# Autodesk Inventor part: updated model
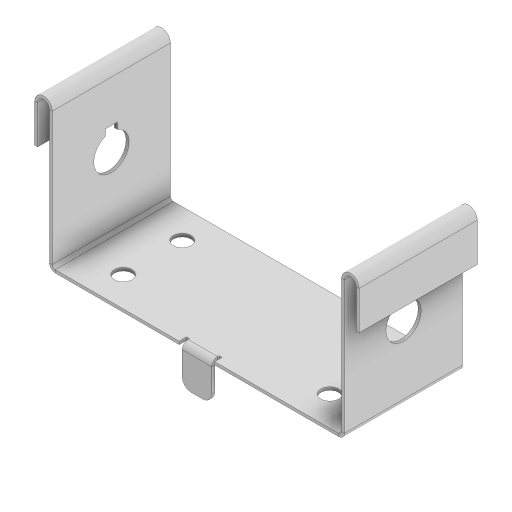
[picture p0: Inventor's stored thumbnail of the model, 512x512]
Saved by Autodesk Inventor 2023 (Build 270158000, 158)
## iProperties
Created: 2021-06
Part Number: updated model
Material: Generic
Document SubType Name: Sheet Metal
Designer: ASUS Laptop
Density: 1 g/cm^3
Flat Pattern Width: 5.12619 cm
Flat Pattern Length: 23.1855 cm
Flat Pattern Area: 118.853 cm^2
Sheet Metal Rule: Default_mm
Sheet Metal Width: 51.262 mm
Sheet Metal Length: 231.855 mm
Sheet Metal Area: 11885.332 mm^2
Appearance: Default
Author: ASUS Laptop
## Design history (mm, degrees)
node "Face1"
  sketch "Sketch2"
    geometry: L1 (0, 0)-(-100, 0); L2 (-100, 0)-(-100, -40); L3 (-100, -40)-(0, -40); L4 (0, -40)-(0, 0)
    constraints: 8 end point, 2 parallel, 1 horizontal, 1 perpendicular
    dimensions: "d0" = 40 distance of L3.end L1.start; "d1" = 100 distance of L2.end L3.end
sketch "Sketch3"
  geometry: L1 (0, 0)-(0, 40) reference; L2 (100, 0)-(0, 0) reference; 1 further point
  dimensions: "d3" = 15 distance from line of L1 point (15, 10); "d4" = 10 distance from line of L2 point (15, 10)
hole "Hole1" sketch "Sketch3" at (15, 10) diameter "d5" = 6; stored, may be unused: countersink angle "d9" = 90 deg, drill point angle "d11" = 118 deg; dims "d6" = 6, "d7" = 6, "d8" = 2, "d10" = 1 (= Thickness)
pattern_linear "Rectangular Pattern1" dims "d14" = 20, "d17" = 70
node "Flange1"
feature "Hem1" dims "d2" = 1 (= Thickness), "d28" = 1 (= BendReliefWidth), "d29" = 0.5 (= BendReliefDepth), "d30" = 2 (= MinimumRemnant), "d31" = 1 (= TransitionRadius), "d32" = 16, "d33" = 4, "d34" = 2 (= 0.5 x d33), "SeamGap" = 0.01
feature "Hem2" dims "d2" = 1 (= Thickness), "d35" = 1 (= BendReliefWidth), "d36" = 0.5 (= BendReliefDepth), "d37" = 2 (= MinimumRemnant), "d38" = 1 (= TransitionRadius), "d39" = 16, "d40" = 4, "d41" = 2 (= 0.5 x d40), "SeamGap" = 0.01
sketch "Sketch7"
  geometry: L1 (0, 0)-(40, 0) reference; L2 (40, 0)-(40, -48) reference; 2 further points
  dimensions: "d42" = 25 distance from line of point (20, -25) L1; "d43" = 20 distance from line of L2 point (20, -25)
feature "iFeature15:1" sketch "Sketch7"
sketch "Sketch8"
  geometry: L1 (40, 0)-(0, 0) reference; L2 (40, -48)-(40, 0) reference; 2 further points
  dimensions: "d50" = 25 distance from line of point (20, -25) L1; "d51" = 20 distance from line of point (20, -25) L2
feature "iFeature15:2" sketch "Sketch8"
node "Flange2"
feature "Corner Round1" dims "d69" = 3
body "Solid1"
face "Plate1" dims "d2" = 1 (= Thickness)
sketch "Sketch4"
  geometry: L1 through (0, -20) direction (-5.44e-32, 1); L2 through (-25, 0) direction (-1, -9.38e-32); L3 (-50, 0)-(-50, -40); L4 (-50, -40)-(0, -40)
  constraints: 6 end point, 1 horizontal, 1 perpendicular, 1 vertical
face "Plate2" dims "d2" = 1 (= Thickness), "d18" = 1 (= BendReliefWidth), "d19" = 0.5 (= BendReliefDepth), "d20" = 2 (= MinimumRemnant), "d21" = 1 (= TransitionRadius), "d22" = 50, "d23" = 90 deg, "d24" = 1 (= BendRadius), "d25" = 4 (= CornerReliefSize), "d26" = 1 (= GapSize), "d27" = 1 (= JacobiRadiusSize), "SeamGap" = 0.01
bend "Bend1" dims "d2" = 1 (= Thickness), "d18" = 1 (= BendReliefWidth), "d19" = 0.5 (= BendReliefDepth), "d20" = 2 (= MinimumRemnant), "d21" = 1 (= TransitionRadius), "d22" = 50, "d23" = 90 deg, "d24" = 1 (= BendRadius), "SeamGap" = 0.01
feature "Corner1" dims "d22" = 50, "d23" = 90 deg, "d25" = 4 (= CornerReliefSize), "d26" = 1 (= GapSize), "d27" = 1 (= JacobiRadiusSize)
sketch "Sketch9"
  geometry: L1 (-53, 0)-(-43, 0); L2 (-43, 0)-(-43, 13); L3 (-43, 13)-(-53, 13); L4 (-53, 13)-(-53, 0)
  constraints: 8 end point
face "Plate3" dims "d2" = 1 (= Thickness), "d58" = 1 (= BendReliefWidth), "d59" = 0.5 (= BendReliefDepth), "d60" = 2 (= MinimumRemnant), "d61" = 1 (= TransitionRadius), "d62" = 10, "d63" = 13, "d64" = 90 deg, "d65" = 1 (= BendRadius), "d66" = 4 (= CornerReliefSize), "d67" = 1 (= GapSize), "d68" = 1 (= JacobiRadiusSize), "SeamGap" = 0.01
bend "Bend2" dims "d2" = 1 (= Thickness), "d58" = 1 (= BendReliefWidth), "d59" = 0.5 (= BendReliefDepth), "d60" = 2 (= MinimumRemnant), "d61" = 1 (= TransitionRadius), "d63" = 13, "d64" = 90 deg, "d65" = 1 (= BendRadius), "SeamGap" = 0.01
feature "Corner2" dims "d63" = 13, "d64" = 90 deg, "d66" = 4 (= CornerReliefSize), "d67" = 1 (= GapSize), "d68" = 1 (= JacobiRadiusSize)
sketch "Sketch5"
  geometry: L1 (1, 0)-(0, 0); L2 (-4, 0)-(-4, -13); L3 (-4, -13)-(-5, -13); L4 (-5, -13)-(-5, 0); A1 r 2 centre (-2, 0) between (0, 0) and (-4, 0); A2 r 3 centre (-2, 0) between (1, 0) and (-5, 0)
  constraints: 8 end point, 4 point on circle
sketch "Sketch6"
  geometry: L1 (1, 0)-(0, 0); L2 (-4, 0)-(-4, -13); L3 (-4, -13)-(-5, -13); L4 (-5, -13)-(-5, 0); A1 r 2 centre (-2, 0) between (0, 0) and (-4, 0); A2 r 3 centre (-2, 0) between (1, 0) and (-5, 0)
  constraints: 8 end point, 4 point on circle
feature "Definition1"
other parameters: "Thickness" = 1 (derived), "BendRadius" = 1 (= Thickness), "BendReliefWidth" = 1 (= Thickness), "BendReliefDepth" = 0.5 (= 0.5 x Thickness), "CornerReliefSize" = 4 (= 4 x Thickness), "MinimumRemnant" = 2 (= 2 x Thickness), "TransitionRadius" = 1 (= BendRadius), "JacobiRadiusSize" = 1 (= BendRadius), "GapSize" = 1 (= Thickness), "d49" = 0, "d57" = 0, "BendRadius" = 1, "BendReliefDepth" = 0.5, "BendReliefWidth" = 1, "CornerReliefSize" = 4, "GapSize" = 1, "JacobiRadiusSize" = 1, "MinimumRemnant" = 2, "Thickness" = 1, "TransitionRadius" = 1
